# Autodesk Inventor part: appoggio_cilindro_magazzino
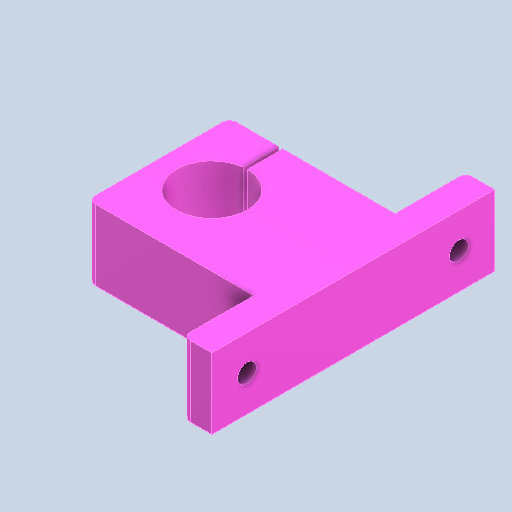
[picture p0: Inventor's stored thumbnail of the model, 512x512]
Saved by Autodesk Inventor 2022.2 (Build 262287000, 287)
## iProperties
Created: 2024-10
Part Number: appoggio_cilindro_magazzino
Material: Alluminio 6061
Document SubType Name: Modeling
Designer: 18907419
Density: 2.7 g/cm^3
Appearance: Default
Author: 18907419
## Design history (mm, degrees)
feature "Solido1"
node "Solido2"
